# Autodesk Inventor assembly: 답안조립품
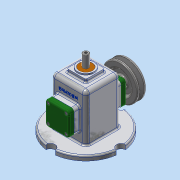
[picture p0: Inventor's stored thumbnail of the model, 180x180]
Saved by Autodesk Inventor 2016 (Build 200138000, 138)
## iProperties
Created: 2018-07
Part Number: 답안조립품
Material: 일반
Document SubType Name: Assembly
Designer: 605-03
Author: 605-03
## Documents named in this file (16)
- C:\Users\605-03\Desktop\480707V1003\답안조립품.iam
- C:\Users\605-03\Desktop\480707V1003\본체.ipt
- C:\Users\605-03\Desktop\480707V1003\편심축.ipt
- C:\Users\605-03\Desktop\480707V1003\베어링 12x32x10.ipt
- C:\Users\605-03\Desktop\480707V1003\앞커버.ipt
- C:\Users\605-03\Desktop\480707V1003\뒤커버.ipt
- C:\Users\605-03\Desktop\480707V1003\오일 실 12 25 7.ipt
- C:\Users\605-03\Desktop\480707V1003\링크.ipt
- C:\Users\605-03\Desktop\480707V1003\V벨트풀리.ipt
- C:\Users\605-03\Desktop\480707V1003\키 4x4x10.ipt
- C:\Users\605-03\Desktop\480707V1003\멈춤나사 M3x8.ipt
- C:\Users\605-03\Desktop\480707V1003\볼트 M4.ipt
- C:\Users\605-03\Desktop\480707V1003\슬라이드.ipt
- C:\Users\605-03\Desktop\480707V1003\핀 5x18.ipt
- C:\Users\605-03\Desktop\480707V1003\고정핀 1.2x8.ipt
- C:\Users\605-03\Desktop\480707V1003\부시.ipt
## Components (3 placed, 3 different names)
1. V벨트풀리:1
2. 핀 5x18:1
3. 고정핀 1.2x8:1
